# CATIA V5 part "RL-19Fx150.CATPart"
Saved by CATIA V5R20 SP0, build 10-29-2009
Part number: _RL-19Fx150
Definition: NONE
Nomenclature: _RL-19Fx150
Source: Unknown
Description: PART-_RL-19Fx150-DESC
Bounding box of the stored display mesh (mm): x -150 to 14, y -10.5 to 10.5, z -10.5 to 10.5
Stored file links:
  C:\Users\Utente\Desktop\IO LAVORO\3D X SITO CF\X SITO\PLASTICA\RLF\RL-19Fx150.CATPart
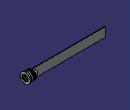
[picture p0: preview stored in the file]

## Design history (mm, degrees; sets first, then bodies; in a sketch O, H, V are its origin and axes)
Body1 "_RL-19Fx150" (main body)
  Solid1: solid without history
